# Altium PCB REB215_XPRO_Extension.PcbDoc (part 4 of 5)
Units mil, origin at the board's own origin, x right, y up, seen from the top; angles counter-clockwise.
Board outline 4055.74 x 2606 mil, 6 copper layers (Top Layer LF-signals, Signal Layer 1, Internal Plane 1, Mid-1, Mid-2, Bottom Layer LF-signals), stack 58.434 mil thick; 278 components, 292 nets, 1282 pads, 1177 vias.
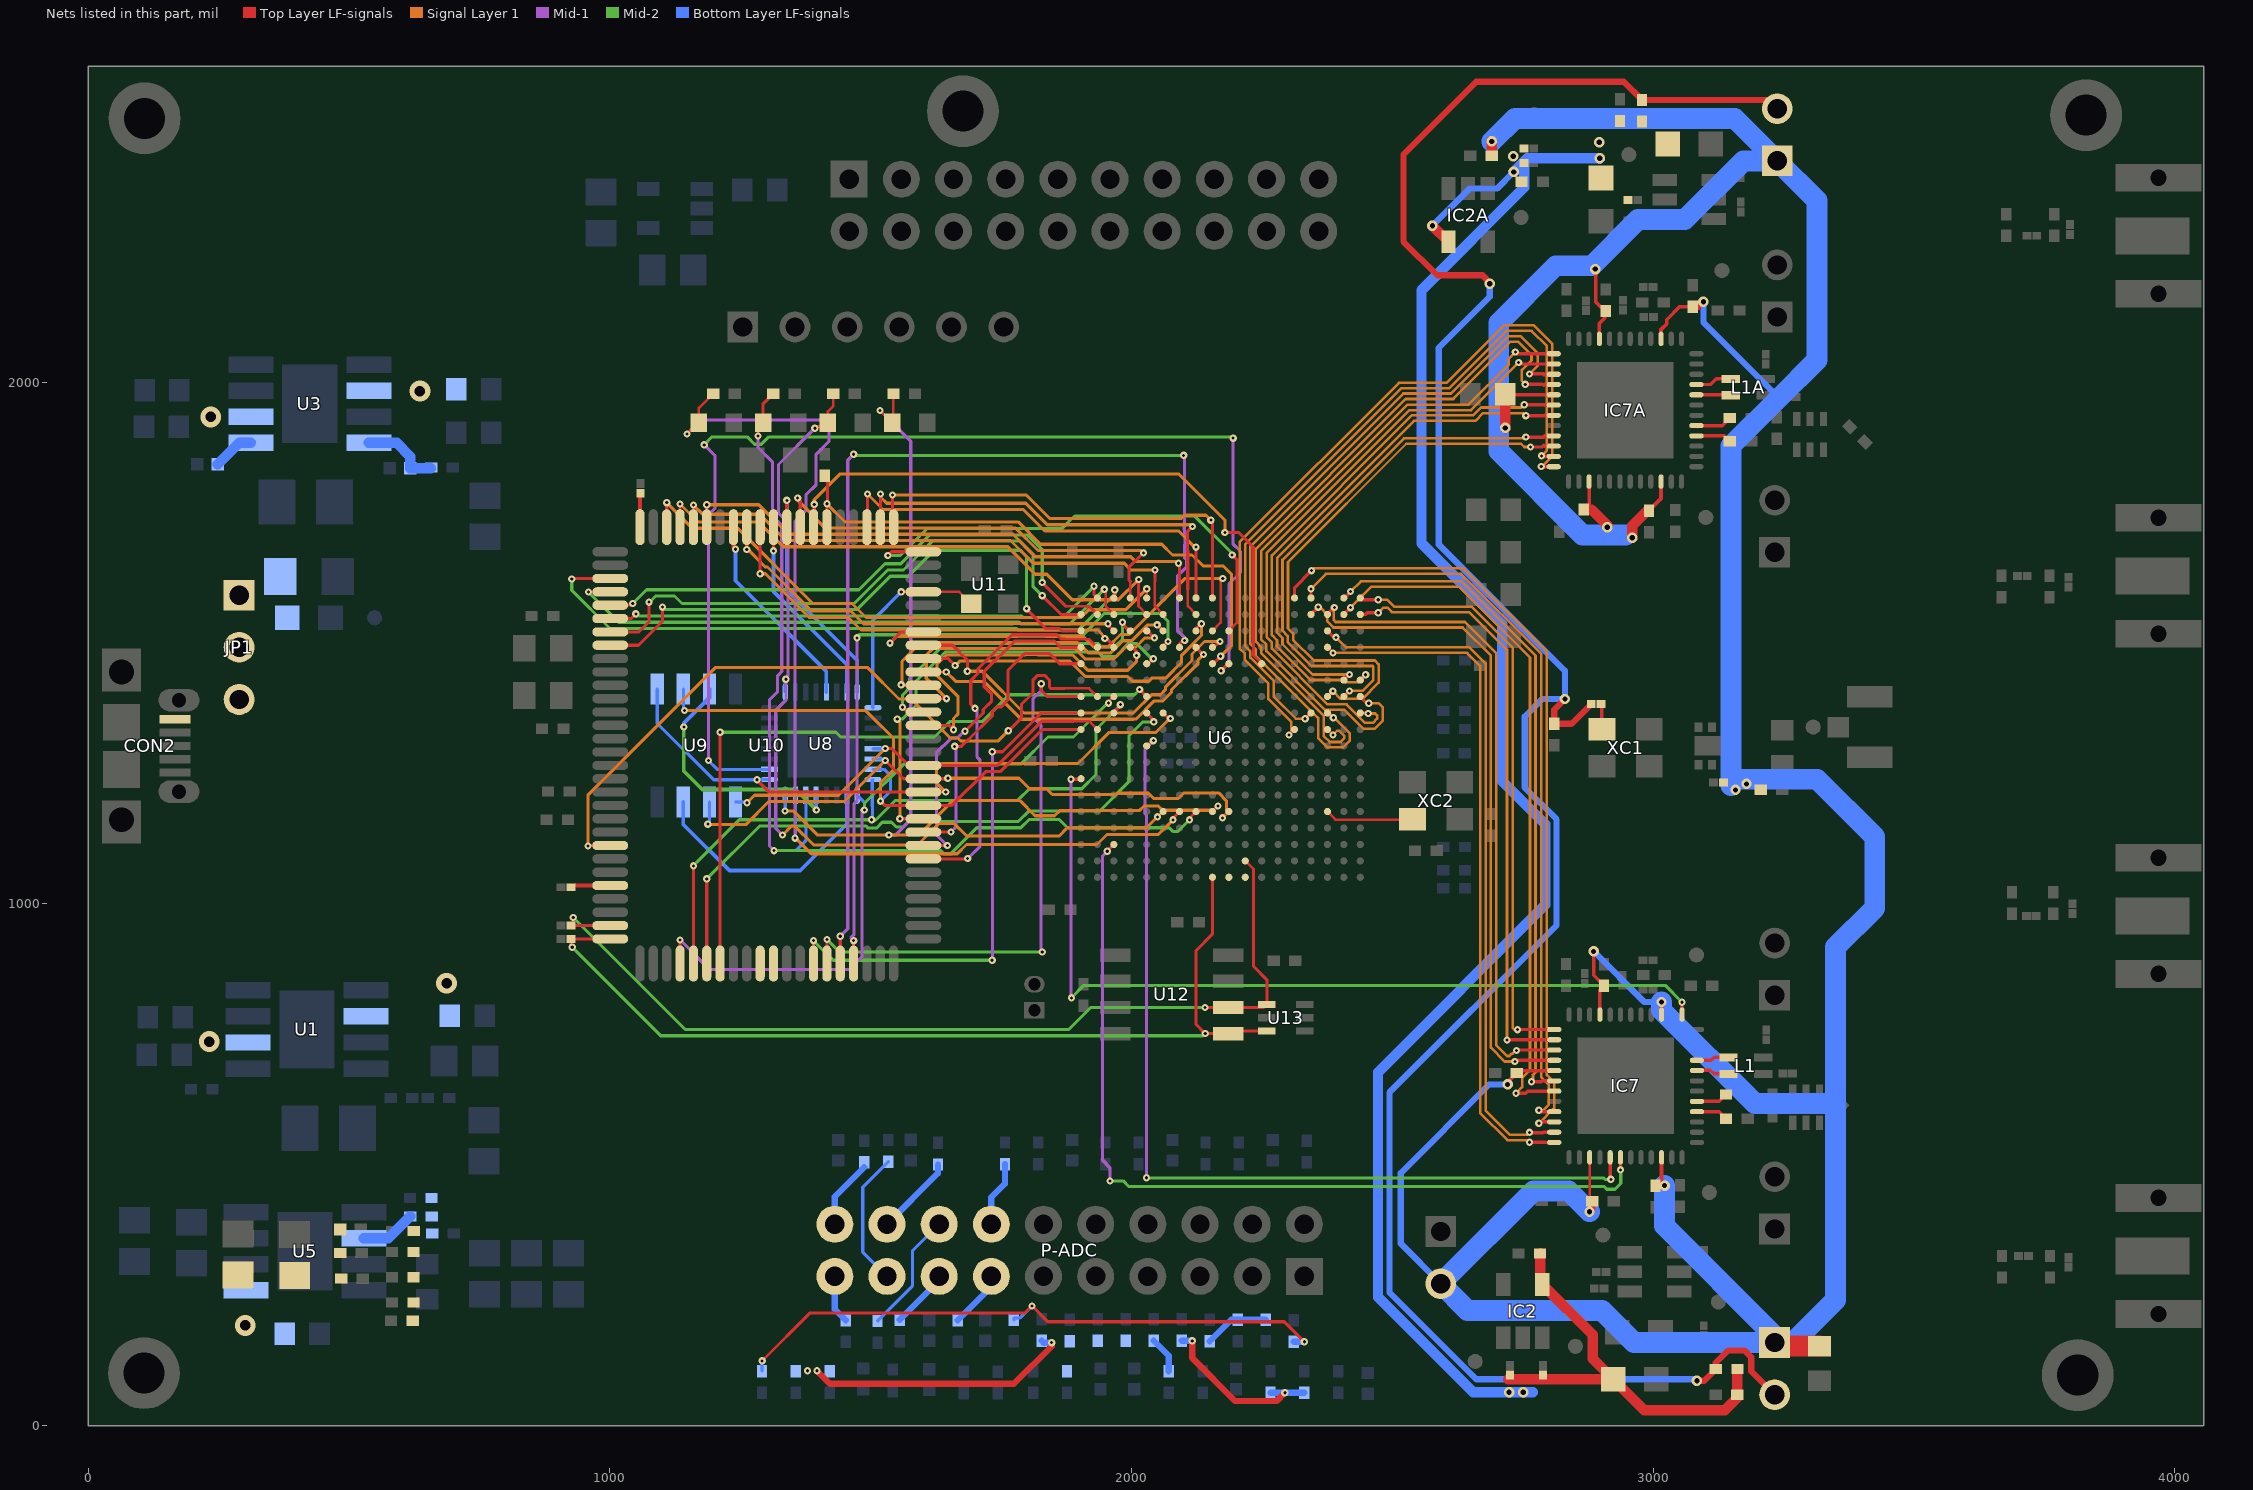
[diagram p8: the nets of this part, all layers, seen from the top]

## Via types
v1: diameter 20, hole 10, Top Layer LF-signals to Bottom Layer LF-signals, 660 vias
v2: diameter 14, hole 6, Top Layer LF-signals to Bottom Layer LF-signals, 470 vias
v3: diameter 40, hole 20, Top Layer LF-signals to Bottom Layer LF-signals, 46 vias
v4: diameter 12, hole 6, Top Layer LF-signals to Bottom Layer LF-signals, 1 vias

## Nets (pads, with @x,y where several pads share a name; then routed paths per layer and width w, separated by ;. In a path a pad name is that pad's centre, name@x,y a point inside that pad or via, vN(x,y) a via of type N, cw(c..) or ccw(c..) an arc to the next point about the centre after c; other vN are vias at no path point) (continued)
NetR17_2: R17.2 U3.5 | length 80.3
  Bottom Layer LF-signals w20: R17.2@248.69,1843 289.47,1883.78 U3.5@312.07,1883.78
NetR018_1: R018.1 U10.100 | length 65.5
  Top Layer LF-signals w7: U10.100@1057.89,1722.31 1057.89,1786.19 R018.1@1059,1787.3
NetR18_1: R18.1 R19.2 U3.4 | length 151.6
  Bottom Layer LF-signals w20: U3.4@538.06,1883.78 591.22,1883.78 617.49,1857.51 R19.2@617.49,1835.41 R18.1@656.71,1835.41
NetR019_1: R019.1 U10.26 | length 72.1
  Top Layer LF-signals w7: R019.1@928.74,1035.3 U10.26@1000.8,1035.3
NetR23_1: R23.1 R24.2 R25.1
NetR23_2: R23.2 U5.6 | length 106.1
  Bottom Layer LF-signals w20: U5.6@528.66,359.18 575.67,359.18 R23.2@617.49,401
NetR40_2: R40.2 R58.2 R65.1 | length 1202.9
  Top Layer LF-signals w6: v2@1291.68,123.68 1384,216 1795.82,216 v2(1809.24,229.42) 1839.66,199 2293,199 v2(2331.41,160.59)
  Bottom Layer LF-signals w6: R58.2@1291.68,104.36 1291.68,123.68 v2(1292,124) ; R40.2@1774.48,202.79 1774.48,206.52 1786.68,206.52 1809.24,229.08 v2(1809.24,229.42) 1810.82,231 v2@1811.16,231
  Bottom Layer LF-signals w12: R65.1@2311.1,160.47 2331.29,160.47 v2(2331.41,160.59)
NetR41_2: R41.2 R57.2 R64.1 | length 124.4
  Bottom Layer LF-signals w12: R64.1@2150.11,161.45 2191.45,202.79 R41.2@2203.77,202.79 R57.2@2257.44,202.79
NetR42_2: R42.2 R56.2 R63.1 | length 336.3
  Top Layer LF-signals w12: v2(2116.49,162.43) 2116.49,129.51 2199,47 2277.98,47 v2(2294,63.03)
  Bottom Layer LF-signals w12: R63.1@2096.45,162.43 v2(2116.49,162.43) ; R42.2@2266.46,63.03 v2(2294,63.03) R56.2@2331.45,63.03
NetR43_2: R43.2 R55.2 R62.1 | length 70
  Bottom Layer LF-signals w12: R62.1@2042.79,162.43 2071.5,133.72 R43.2@2071.5,104.36
NetR44_2: R44.2 R54.2 R61.1
NetR45_2: R45.2 R53.2 R60.1 | length 518.3
  Top Layer LF-signals w12: v2(1397,105) 1422,80 1774.74,80 1847,152.26 v2(1847,159)
  Bottom Layer LF-signals w6: v2(1847,159) v2@1847,160.04
  Bottom Layer LF-signals w12: R60.1@1828.14,162.43 1831.58,159 v2(1847,159)
  other v2: 1379,105
NetR46_2: 
NetU6_E3: U6.E3 XC2.3 | length 170.3
  Top Layer LF-signals w5: U6.E3@2375.64,1177.04 2390.94,1161.74 2455.51,1161.74 2455.62,1161.63 2468.38,1161.63 2468.49,1161.74 2538.72,1161.74 XC2.3@2538.72,1162.57
NetU8_10: U8.10 U9.7 | length 485.1
  Bottom Layer LF-signals w7: U9.7@1141,1195.47 1141,1152.29 1229.29,1064 1364.82,1064 1454.6,1153.78 U8.10@1454.6,1208.31
NetU8_13: U8.13 U9.3 | length 499.1
  Mid-2 w7: v2(1142,1339) 1142,1254.34 1177,1219.34 1356.66,1219.34 v2(1396,1180)
  Bottom Layer LF-signals w7: v2(1142,1339) 1142,1346.69 1191,1395.69 U9.3@1191,1412 ; U8.13@1395.5,1208.31 1395.5,1180.5 v2(1396,1180) 1396,1187.84
NetW2_1: W2.1 XC1.4 | length 46.4
  Top Layer LF-signals w7: XC1.4@2901.88,1335 W2.1@2901.88,1381.44
PA0: U6.R15 U10.67 | length 650.7
  Top Layer LF-signals w6: U10.67@1601.2,1342.39 1650.61,1342.39 v2(1659,1334) ; U6.R15@1997.69,1492 2001,1492 2009.91,1483.1 v2(2009.91,1476.51)
  Signal Layer 1 w6: v2(1659,1334) 1659,1355.39 1658.95,1355.45 1667.17,1363.67 1667.17,1398.09 1627,1438.26 1627,1459.34 1645.13,1477.47 1797.14,1477.47 1797.48,1477.81 1820.52,1477.81 1820.86,1477.47 1886.99,1477.47 1916.46,1448 1993,1448 2009.91,1464.91 v2(2009.91,1476.51)
PA1: U6.T15 U10.68 | length 613
  Top Layer LF-signals w6: v2(1561,1377) 1566,1372 1605.22,1372 U10.68@1601.2,1367.98 ; v2(1983,1540) 1983,1536 1995.5,1523.5 U6.T15@1997.69,1523.5
  Mid-2 w6: v2(1561,1377) 1561,1400.06 1574.36,1413.41 1574.36,1431.27 1642.08,1499 1936.51,1499 1942.41,1493.1 1968.09,1493.1 1983,1508 v2(1983,1540)
PA2: U6.T14 U10.69 | length 632.5
  Top Layer LF-signals w6: U10.69@1601.2,1393.57 v2(1645.57,1393.57) ; U6.T14@2029.19,1523.5 2030.5,1523.5 v2(2044,1510)
  Signal Layer 1 w6: v2(1645.57,1393.57) 1606.54,1432.6 1606.54,1477.09 1618.82,1489.38 1792.21,1489.38 1792.55,1489.72 1825.45,1489.72 1825.79,1489.38 1891.92,1489.38 1912.02,1469.28 1965.45,1469.28 1988.81,1492.64 2008.64,1492.64 2026,1510 v2(2044,1510)
PA3: U6.T13 U10.70 | length 640.2
  Top Layer LF-signals w6: v2(1558.45,1420) 1559.29,1419.16 U10.70@1601.2,1419.16 ; v2(2049.18,1535) U6.T13@2060.68,1523.5
  Signal Layer 1 w6: v2(1558.45,1420) 1560,1421.55 1560,1465.1 1596.19,1501.28 1787.28,1501.28 1787.62,1501.62 1830.38,1501.62 1830.72,1501.28 1896.86,1501.28 1916.95,1481.19 1960.52,1481.19 1983.88,1504.55 2000.55,1504.55 2031,1535 v2(2049.18,1535)
PA4: U6.R11 U10.71 | length 657.6
  Top Layer LF-signals w6: U10.71@1601.2,1444.75 v2(1644.98,1444.75) ; U6.R11@2123.67,1492 2137.67,1478 v2(2138,1478)
  Signal Layer 1 w6: v2(1644.98,1444.75) 1663.17,1426.57 1716.6,1426.57 1789.05,1354.11 2003.86,1354.11 2004.07,1354.32 2008.78,1354.32 2043.65,1389.19 2060.52,1389.19 2076.81,1405.48 2076.81,1410.64 2127.84,1461.67 2127.84,1467.84 v2(2138,1478) 2135.67,1478 v2@2133.67,1480
PA5: U6.T11 U10.72 | length 643.7
  Top Layer LF-signals w6: U10.72@1601.2,1470.34 1648.66,1470.34 v2(1662,1457) ; U6.T11@2123.67,1523.5 2123.67,1526.67 2123,1527.35 2132.65,1537 v2(2134,1537)
  Signal Layer 1 w6: v2(1662,1457) 1670.57,1465.57 1802.07,1465.57 1802.41,1465.91 1815.59,1465.91 1815.93,1465.57 1882.06,1465.57 1911.72,1435.91 1992.59,1435.91 2001.59,1426.91 2032.98,1426.91 2038.98,1432.91 2065.4,1432.91 2096.18,1463.68 2096.18,1476.68 2134,1514.51 v2(2134,1537)
PA6: U6.R10 U10.73 | length 721.5
  Top Layer LF-signals w6: U10.73@1601.2,1495.93 1657.07,1495.93 1685.35,1467.65 v2(1685.35,1446) ; U6.R10@2155.17,1492 2158,1492 2169.14,1503.14 v2(2169.81,1503.14)
  Signal Layer 1 w6: v2(1685.35,1446) 1714,1446 1793.98,1366.02 1998.93,1366.02 1999.14,1366.22 2003.84,1366.22 2038.72,1401.1 2055.59,1401.1 2064.91,1410.41 2064.91,1415.58 2115.93,1466.6 2115.93,1479.09 2139.98,1503.14 v2(2169.81,1503.14)
PA7: U6.T10 U10.74 | length 886.6
  Top Layer LF-signals w5: U6.T10@2155.17,1523.5 2170.92,1539.24 v2@2170.92,1618.38
  Top Layer LF-signals w6: v2(1537,1500) 1558.52,1521.52 U10.74@1601.2,1521.52 ; v2@2170.92,1619.92 v2(2175,1624)
  Signal Layer 1 w6: v2(1537,1500) 1550.19,1513.19 1782.35,1513.19 1782.69,1513.53 1835.31,1513.53 1835.65,1513.19 1907.11,1513.19 1927.2,1493.1 1955.59,1493.1 1978.95,1516.45 1995.62,1516.45 2103.16,1624 v2(2175,1624)
PB0: U6.M16 U8.9 U10.34 | length 1325.3
  Top Layer LF-signals w6: U10.34@1134.66,885.69 v2(1134.66,931) ; v2(1956,1385) 1956,1388 1965.51,1397.51 U6.M16@1966.19,1397.51
  Mid-1 w6: v2(1134.66,931) 1191.66,874 1459,874 1483.24,898.24 1483.24,1179.76 1483.49,1180 v2(1488,1180)
  Mid-2 w6: v2(1488,1180) 1488,1192.54 1563.47,1268 1788,1268 1840,1320 1889,1320 1954,1385 v2(1956,1385)
  Bottom Layer LF-signals w6: U8.9@1474.3,1208.31 1488,1194.61 v2(1488,1180)
PB1: U6.L16 U8.8 U10.35 | length 1287.4
  Top Layer LF-signals w6: U10.35@1160.25,885.69 v2(1160.25,1073) ; U6.L16@1966.19,1366.02 1966.19,1367.19 1980,1381 1979.02,1381.98 v2(1978.66,1381.98)
  Mid-2 w6: v2(1160.25,1073) 1160.25,1073.25 1248.27,1161.27 v2(1502,1161.27) 1510.27,1161.27 1547.53,1198.53 1782.03,1198.53 1804.41,1220.91 1904.91,1220.91 1932,1248 1932,1334.51 1979.48,1381.98 v2(1978.66,1381.98)
  Bottom Layer LF-signals w6: v2(1502,1161.27) 1503.91,1163.17 1503.91,1186.59 1503.09,1187.4 1503.09,1237.1 U8.8@1504.35,1238.36
PB2: U6.L14 U10.36 | length 1228.9
  Top Layer LF-signals w6: U10.36@1185.84,885.69 v2(1185.84,1048) ; U6.L14@2029.19,1366.02 2042.79,1352.41 v2(2042.79,1349)
  Mid-2 w6: v2(1185.84,1048) 1287.21,1149.36 1491.41,1149.36 1495.41,1145.36 1511.2,1145.36 1522.5,1156.66 1540.09,1156.66 1549.41,1147.35 1562.59,1147.35 1573.24,1158 1783,1158 1802.97,1177.97 1938.67,1177.97 1995,1234.31 1995,1321.91 2022.09,1349 v2(2042.79,1349)
PB3: U6.M14 U10.37 | length 1305.5
  Top Layer LF-signals w6: U10.37@1211.43,885.69 v2(1211.43,1329) ; v2(2015.7,1411) U6.M14@2029.19,1397.51
  Mid-2 w6: v2@1215,1326.98 1217.02,1329 1433.48,1329 1442.48,1320 1622.51,1320 1652.41,1349.91 1714.74,1349.91 1733.09,1368.26 1733.09,1368.59 1742.41,1377.91 1742.74,1377.91 1765.93,1401.1 2005.79,1401.1 v2(2015.7,1411)
PB4: U6.L18 U10.44 | length 1003.1
  Top Layer LF-signals w6: U10.44@1390.57,885.69 v2(1390.57,929.57) ; v2(1733.1,1291.79) 1752.7,1291.79 1826.92,1366.02 U6.L18@1903.2,1366.02
  Mid-1 w6: v2(1733,892) 1733.72,892.72 1733.72,1291.17 v2(1733.1,1291.79)
  Mid-2 w6: v2(1390.57,929.57) 1428.13,892 v2(1733,892)
PB5: U6.M18 U10.45 | length 1091.5
  Top Layer LF-signals w6: U10.45@1416.16,885.69 v2(1416.16,931.98) ; v2(1827,1422.18) 1827,1409.13 1838.49,1397.65 ; 1838.49,1397.51 1838.49,1397.65 ; U6.M18@1903.2,1397.51 1838.62,1397.51 1838.49,1397.65
  Mid-1 w6: v2(1827,1422.18) 1827,1409 1810.99,1392.99 1810.99,1358.21 1826.91,1342.3 1826.91,910.1 v2(1829,908)
  Mid-2 w6: v2(1416.16,931.98) 1440.14,908 v2(1829,908)
PB6: U6.R12 U10.46 | length 2014.1
  Top Layer LF-signals w6: U10.46@1441.75,885.69 v2(1441.75,938) ; U6.R12@2089,1492 U6.R12@2092.18,1492 2092.18,1498.92 2098.26,1505 v2(2102,1505)
  Mid-1 w6: v2(1441.75,938) 1456,952.25 1456,1850.66 v2(1467.34,1862) ; v2(2100.09,1859.91) 2102,1858 2102,1730.87 2101.09,1729.97 2101.09,1716.79 2102,1715.88 2102,1703.49 2102.91,1702.59 2102.91,1689.41 2102,1688.51 2102,1663.49 2105.91,1659.59 2105.91,1646.41 2088,1628.51 2088,1524.33 2102,1510.33 v2(2102,1505)
  Mid-2 w6: v2@1467.34,1859.91 v2(2100.09,1859.91)
PB7: U6.R13 U10.47 | length 1315.8
  Top Layer LF-signals w6: U10.47@1467.34,885.69 v2(1467.34,929.66) ; U6.R13@2060.68,1492 2060.68,1494.15 2061.15,1494.15 v2(2070,1503) v2@2072,1505
  Mid-1 w6: v2(1467.34,929.66) 1462,935 1467.91,940.91 1467.91,1191.4 1474,1197.49 v2(1474,1510)
  Mid-2 w6: v2(1474,1510) 1472.19,1510 1478.28,1516.1 1774.9,1516.1 1777.62,1513.38 1904.38,1513.38 1947.7,1556.7 2055.3,1556.7 2070,1542 v2(2070,1503)
PC0: U6.R17 U10.57 | length 737.5
  Top Layer LF-signals w5: 1871.31,1507.75 1918.95,1507.75 U6.R17@1934.7,1492
  Top Layer LF-signals w6: U10.57@1601.2,1086.48 1685.48,1086.48 v2(1686,1087) ; v2(1700,1375) 1692,1383 1692,1428 1705.93,1441.93 1705.93,1450.77 1771.1,1515.93 1857.28,1515.93 1865.46,1507.75 1871.31,1507.75
  Mid-1 w6: v2(1686,1087) 1709.91,1110.91 1709.91,1275.65 1704.09,1281.46 1704.09,1370.91 v2(1700,1375)
PC1: U6.R18 U10.58 | length 661.2
  Top Layer LF-signals w6: U10.58@1601.2,1112.07 1646.93,1112.07 v2(1647,1112) ; v2(1681,1331) 1715.91,1365.91 1715.91,1372.82 1731.91,1388.82 1731.91,1402 1717.84,1416.07 1717.84,1445.84 1776.03,1504.03 1852.35,1504.03 1864.38,1492 U6.R18@1903.2,1492
  Mid-1 w6: v2(1647,1112) 1626,1133 1626,1289.49 1654.41,1317.91 1665.91,1317.91 1680,1332 v2(1681,1331)
PC2: U6.P18 U10.59 | length 583.2
  Top Layer LF-signals w6: U10.59@1601.2,1137.66 1653.66,1137.66 v2(1654,1138) ; v2(1661,1302) 1674,1302 1687.09,1315.1 1687.59,1315.1 1733.09,1360.6 1733.09,1368.59 1742.41,1377.91 1750.4,1377.91 1763.43,1390.94 1763.43,1447.76 1795.89,1480.22 1842.49,1480.22 1862.2,1460.5 U6.P18@1903.2,1460.5
  Mid-1 w6: v2(1654,1138) 1663.95,1147.95 v2@1663.95,1299.05 ; v2@1661,1299.05 v2(1661,1302)
PC3: U6.P14 U10.60 | length 853.3
  Top Layer LF-signals w6: v2(1556,1163.25) U10.60@1601.2,1163.25 ; U6.P14@2029.19,1460.5 2032.5,1460.5 v2(2042,1470)
  Mid-2 w6: v2(1551,1354.18) 1560.68,1354.18 1587,1380.51 1587,1427.08 1642.83,1482.91 1935.76,1482.91 1944.67,1474 1969.55,1474 1994.96,1499.41 2009.49,1499.41 v2@2038.9,1470 ; v2@2038.51,1470 v2@2038.9,1470 ; v2(2042,1470) v2@2038.9,1470
  Signal Layer 1 w6: v2(1551,1354.18) 1556,1349.18 v2(1556,1163.25)
PC4: U6.K18 U8.7 U9.2 U10.61 | length 1136.4
  Top Layer LF-signals w6: v2(1519,1197) 1527.16,1188.84 U10.61@1601.2,1188.84 1655.68,1188.84 1720.55,1253.71 1748.29,1253.71 1829.1,1334.52 U6.K18@1903.2,1334.52
  Signal Layer 1 w6: v2(1143,1371) 1490,1371 1543.97,1317.03 1543.97,1257.3 1519,1232.33 v2(1519,1197)
  Bottom Layer LF-signals w6: v2@1141,1373 U9.2@1141,1412 ; U8.7@1504.35,1258.06 1525.94,1258.06 1538.38,1245.62 1538.38,1216.38 v2(1519,1197)
PC5: U6.L13 U8.17 U9.1 U10.62 | length 1260.4
  Top Layer LF-signals w6: v2@1285.84,1238.36 1282.36,1238.36 v2(1282,1238) 1305.57,1214.43 U10.62@1601.2,1214.43 v2(1644,1214.43) ; U6.L13@2060.68,1366.02 2060.68,1366.68 2071.76,1355.6 v2(2074.6,1355.6)
  Signal Layer 1 w6: v2(1644,1214.43) 1626,1232.43 1626,1257.53 1637.57,1269.1 1897.56,1269.1 1957.37,1328.91 2046.91,1328.91 2073.6,1355.6 v2(2074.6,1355.6)
  Bottom Layer LF-signals w6: U9.1@1091,1412 1091,1346 1199,1238 v2(1282,1238) ; v2@1282.36,1238.36 U8.17@1306.35,1238.36
PC6: U6.E9 U8.6 U9.6 U10.63 | length 1205.2
  Top Layer LF-signals w6: v2@1528,1275 1562.98,1240.02 U10.63@1601.2,1240.02 1649.02,1240.02 v2(1648.05,1241) ; v2(2174.63,1165) U6.E9@2186.67,1177.04
  Signal Layer 1 w6: v2(1188,1153) 1188,1152 1260.59,1152 1304.99,1196.4 1449.4,1196.4 v2(1528.07,1275.07) ; v2(1648.05,1241) 1784.32,1241 1804.41,1220.91 1837.41,1220.91 1848.41,1209.91 1970.6,1209.91 1972.89,1212.2 2032.31,1212.2 2042.51,1202 2089.79,1202 2100.7,1212.91 2167.09,1212.91 2182,1198 2182,1172.37 v2(2174.63,1165)
  Bottom Layer LF-signals w6: v2@1191,1156 U9.6@1191,1195.47 ; U8.6@1504.35,1277.76 v2@1525.38,1277.76
PC7: U6.K17 U8.5 U9.5 U10.64 | length 814.2
  Top Layer LF-signals w5: 1889.21,1350.27 1918.95,1350.27 U6.K17@1934.7,1334.52
  Top Layer LF-signals w6: v2(1528,1298) 1540.25,1298 1572.64,1265.61 U10.64@1601.2,1265.61 1743.36,1265.61 1828.01,1350.27 1889.21,1350.27
  Signal Layer 1 w6: v2(1263,1194) 1277.31,1208.31 1438.31,1208.31 v2(1528,1298)
  Bottom Layer LF-signals w6: U9.5@1241,1195.47 v2@1261.54,1195.47 ; U8.5@1504.35,1297.46 1527.46,1297.46 v2(1528,1298)
PD0: U6.T9 U10.80 | length 951.2
  Top Layer LF-signals w5: U6.T9@2186.67,1523.5 2202.41,1539.24 2202.41,1618.38
  Top Layer LF-signals w6: v2(1533,1668) 1540.06,1675.06 U10.80@1601.2,1675.06 ; v2(2193,1669) 2202.41,1659.59 2202.41,1618.38
  Mid-2 w6: v2(1533,1668) 1557,1668 1609,1720 1867,1720 1886.09,1739.1 1887.59,1739.1 1892.51,1744.02 2120.66,1744.02 2193,1671.68 v2(2193,1669)
PD1: U6.V10 U10.81 | length 848.5
  Top Layer LF-signals w6: v2(1542,1784) 1542,1724.42 U10.81@1544.11,1722.31 ; v2(2152.25,1735.75) 2155.17,1732.83 U6.V10@2155.17,1586.49
  Signal Layer 1 w6: v2(1542,1784) 1798.51,1784 1843.79,1738.72 2094.79,1738.72 2101.08,1745 2143,1745 v2(2152.25,1735.75)
PD2: U6.U11 U10.82 | length 866.7
  Top Layer LF-signals w5: 2107.93,1603 2107.93,1570.74 U6.U11@2123.67,1554.99
  Top Layer LF-signals w6: U10.82@1518.52,1722.31 1519,1722.79 v2(1519,1785.84) ; 2107.93,1603 2107.93,1677.25 2107.77,1677.41 2107.77,1714.15 v2(2117,1723.38)
  Signal Layer 1 w6: v2(1519,1785.84) 1519,1780 1530.91,1768.1 1797.58,1768.1 1838.86,1726.81 v2@2113.57,1726.81 ; v2@2115.26,1722.31 v2@2115.93,1722.31 ; v2@2115.93,1723.38 v2(2117,1723.38)
PD3: U6.V11 U10.83 | length 831.2
  Top Layer LF-signals w5: U6.V11@2123.67,1586.49 2123.67,1618.38
  Top Layer LF-signals w6: U10.83@1492.93,1722.31 1494,1723.38 v2(1494,1785.84) ; 2123.67,1618.38 v2(2123.67,1684)
  Signal Layer 1 w6: v2(1494,1785.84) 1523.65,1756.19 1792.64,1756.19 1833.93,1714.91 2090.59,1714.91 v2@2121.49,1684
PD4: U6.V12 U10.95 | length 1062.6
  Top Layer LF-signals w5: U6.V12@2092.18,1586.49 2092.18,1602.43
  Top Layer LF-signals w6: U10.95@1185.84,1722.31 v2(1185.84,1765.16) ; v2(2090,1653) 2092.18,1650.82 2092.18,1602.43
  Signal Layer 1 w6: v2(1185.84,1765.16) 1285.84,1765.16 1342.43,1708.57 1772.92,1708.57 1815.89,1665.6 1998.59,1665.6 2008.09,1656.1 2089.91,1656.1 2090,1656 v2(2090,1653)
PD5: U6.U13 U10.96 | length 1070.5
  Top Layer LF-signals w5: 2044.93,1618.38 2044.93,1570.74 U6.U13@2060.68,1554.99
  Top Layer LF-signals w6: U10.96@1160.25,1722.31 v2(1160.25,1764.79) ; 2044.93,1618.38 2044.93,1639.93 v2(2045,1640)
  Signal Layer 1 w6: v2(1160.25,1764.79) 1178.05,1747 1287.16,1747 1337.5,1696.66 1767.99,1696.66 1811.65,1653 1986.19,1653 1999.19,1640 v2(2045,1640)
PD6: U6.U14 U10.97 | length 1096.9
  Top Layer LF-signals w5: v2@2013.44,1618.38 2013.44,1570.74 U6.U14@2029.19,1554.99
  Top Layer LF-signals w6: U10.97@1134.66,1722.31 v2(1134.66,1766.71) ; v2@2013.44,1618.38 2013.44,1625.56 2014,1625 v2(2014,1622)
  Signal Layer 1 w6: v2(1134.66,1766.71) 1169.37,1732 1285.33,1732 1332.57,1684.76 1763.06,1684.76 1815.91,1631.91 1837.91,1631.91 1886.81,1583 1975,1583 v2(2014,1622)
PD7: U6.V14 U10.98 | length 1098.7
  Top Layer LF-signals w5: U6.V14@2029.19,1586.49 v2(2029.19,1604)
  Top Layer LF-signals w6: U10.98@1109.07,1722.31 v2(1109.07,1769.33)
  Signal Layer 1 w6: v2(1109.07,1769.33) 1158.31,1720.1 1244.97,1720.1 1389.06,1576 1464.17,1576 1491.07,1549.1 1767.74,1549.1 1767.89,1549.24 1850.11,1549.24 1850.26,1549.1 1903.09,1549.1 1918,1564 1989.19,1564 v2(2029.19,1604)
PE0: R15B.2 U6.P10 U10.86 | length 1119.7
  Top Layer LF-signals w6: R15B.2@1412.25,1820.66 1417,1815.91 1417,1767.89 v2(1416.16,1767.05) U10.86@1416.16,1722.31 ; U6.P10@2155.17,1460.5 2156.5,1460.5 v2(2170.92,1474.92)
  Signal Layer 1 w6: v2(1416.16,1767.05) 1450.83,1732.38 1782.78,1732.38 1825.75,1689.41 2058.14,1689.41 2078.55,1669 2116.18,1669 2137.18,1648 2175.53,1648 2192,1631.53 2192,1496 v2(2170.92,1474.92)
PE1: U6.P7 U10.87 | length 1217.6
  Top Layer LF-signals w5: 2233.91,1618.38 2233.91,1476.25 U6.P7@2249.66,1460.5
  Top Layer LF-signals w6: U10.87@1390.57,1722.31 1392,1723.74 v2(1392,1766) ; v2(2179,1712) 2206,1712 2233.91,1684.09 2233.91,1618.38
  Signal Layer 1 w6: v2(1392,1766) 1392,1775.13 1440.77,1823.91 2091.01,1823.91 2179,1735.92 v2(2179,1712)
PE2: U6.V15 U10.88 | length 865.9
  Top Layer LF-signals w5: U6.V15@1997.69,1586.49 1997.69,1618.38
  Top Layer LF-signals w6: v2(1360,1778) 1364.98,1773.02 U10.88@1364.98,1722.31 ; 1997.69,1618.38 1995.09,1620.97 1995.09,1645.1 v2(2023,1673)
  Signal Layer 1 w6: v2(1360,1778) 1360,1773.64 1413.17,1720.47 1777.85,1720.47 1820.82,1677.5 2018.5,1677.5 v2(2023,1673)
PE3: U8.32 U10.89 | length 474.5
  Top Layer LF-signals w7: U10.89@1339.39,1722.31 v2(1339.39,1773.61)
  Bottom Layer LF-signals w7: v2(1339.39,1773.61) 1339.39,1601.61 1474.3,1466.7 U8.32@1474.3,1406.31
PE4: U8.31 U10.90 | length 374.3
  Top Layer LF-signals w6: v2(1313.8,1676.86) U10.90@1313.8,1722.31
  Bottom Layer LF-signals w7: v2(1313.8,1676.86) 1313.8,1599.09 1454.6,1458.28 U8.31@1454.6,1406.31
PE5: U6.R16 U10.91 | length 832.2
  Top Layer LF-signals w6: v2(1288.21,1633) U10.91@1288.21,1722.31 ; v2(1949,1509) 1952,1509 1966.19,1494.81 U6.R16@1966.19,1492
  Signal Layer 1 w6: v2(1288.21,1633) 1298.39,1633 1382.29,1549.1 1457.4,1549.1 1481.4,1525.1 1777.42,1525.1 1777.76,1525.43 1840.25,1525.43 1840.58,1525.1 1935.07,1525.1 1952.26,1507.91 v2@1953.09,1507.91
PE6: U6.T16 U10.92 | length 814.8
  Top Layer LF-signals w6: v2(1262.61,1679.61) U10.92@1262.61,1722.31 ; v2(1955,1537) 1955,1534.69 U6.T16@1966.19,1523.5
  Signal Layer 1 w6: v2(1262.61,1679.61) 1264.08,1679.61 1297.7,1646 1302.23,1646 1386.23,1562 1461.33,1562 1486.33,1537 1772.49,1537 1772.82,1537.34 1845.18,1537.34 1845.52,1537 v2(1955,1537) v2@1956.6,1538.6
PE7: U8.29 U10.93 | length 391.8
  Top Layer LF-signals w7: U10.93@1237.02,1722.31 1237.02,1683.98 v2(1241,1680) v2@1239,1680
  Bottom Layer LF-signals w7: v2(1241,1680) 1241,1619.59 1415.2,1445.39 U8.29@1415.2,1406.31
PROG_B: U6.P9 U8.18 | length 2263.8
  Top Layer LF-signals w6: v2(2172,1447) 2185.5,1460.5 U6.P9@2186.67,1460.5
  Mid-1 w6: v2(1181,1880) 1201.75,1859.25 1201.75,1758.57 1189,1745.82 v2(1189,1275) ; v2(2172,1447) 2187.09,1462.1 2187.09,1613.6 2208.91,1635.41 2208.91,1675.59 2194.91,1689.59 v2(2194.91,1893)
  Mid-2 w6: v2(1181,1880) 1181,1880.42 1195.91,1895.32 1263.18,1895.32 1277.41,1881.1 1290.59,1881.1 1304.82,1895.32 2192.58,1895.32 v2(2194.91,1893)
  Bottom Layer LF-signals w6: v2(1189,1275) 1205.94,1258.06 U8.18@1306.35,1258.06
R\E\S\E\T\: U8.1 U10.77 U11.2 | length 387.8
  Top Layer LF-signals w5: U10.77@1601.2,1598.29 1669.87,1598.29 U11.2@1692.57,1575.6
  Top Layer LF-signals w7: v2(1558.7,1598.29) U10.77@1601.2,1598.29
  Bottom Layer LF-signals w7: U8.1@1504.35,1376.26 1504.35,1543.94 v2(1558.7,1598.29)
R\S\T\N\: IC7.13@3055.51,787.82 U6.G18 | length 1659.6
  Top Layer LF-signals w6: v2(1884,1239) 1902.17,1239 U6.G18@1903.2,1240.03 ; IC7.13@3055.51,787.82 v2(3055.51,811.49)
  Mid-1 w6: v2(1884,1239) 1884,822.2 1882,820.2 1882.2,820 v2(1885,820)
  Mid-2 w6: v2@1885,820.42 1908.41,843.83 3023.17,843.83 v2(3055.51,811.49)
RDX0: U10.41
RDY0: U6.V16 U10.3 | length 1221
  Top Layer LF-signals w6: v2(927,1622.88) 928,1623.88 U10.3@1000.8,1623.88 ; U6.V16@1966.19,1586.49 1966.19,1592.43 1966,1592.62 1968,1594.62 v2(1968,1602)
  Mid-2 w6: v2(927,1622.88) 927,1601.42 1000.42,1528 1779.83,1528 1782.55,1525.28 1899.05,1525.28 1968,1594.24 v2(1968,1602)
RDY1: U6.U16 U10.4 | length 1140.9
  Top Layer LF-signals w5: v2@1950.45,1603 1950.45,1570.74 U6.U16@1966.19,1554.99
  Top Layer LF-signals w6: v2@962,1598 v2(959,1598) 959.29,1598.29 U10.4@1000.8,1598.29
  Mid-2 w6: v2(959,1598) 1017.09,1539.91 1784.76,1539.91 1787.48,1537.19 1882.19,1537.19 v2(1948,1603)
RDY2: U6.U17 U10.5 | length 1089.6
  Top Layer LF-signals w5: 1874.26,1570.74 1918.95,1570.74 U6.U17@1934.7,1554.99
  Top Layer LF-signals w6: U10.5@1000.8,1572.7 1001.1,1573 1041,1573 v2(1044,1576) ; v2(1829,1616) 1874.26,1570.74
  Mid-2 w6: v2(1044,1576) 1070.24,1602.24 1477.76,1602.24 1527.62,1652.1 1557.93,1652.1 1613.31,1707.47 1800.18,1707.47 1829,1678.66 v2(1829,1616)
RDY3: U6.V17 U10.6 | length 988.6
  Top Layer LF-signals w6: U10.6@1000.8,1547.11 1041.11,1547.11 v2(1050,1556) ; v2(1928,1609) 1928,1593.19 U6.V17@1934.7,1586.49
  Mid-2 w6: v2@1050,1551.81 v2(1050,1556) 1054.19,1551.81 1789.7,1551.81 1792.41,1549.1 1869.09,1549.1 1928,1608 v2(1928,1609)
RDY4: U6.U18 U10.7 | length 1102.8
  Top Layer LF-signals w6: U10.7@1000.8,1521.52 1055.85,1521.52 1075,1540.67 v2(1075,1578.5) ; v2(1829,1591) 1865.01,1554.99 U6.U18@1903.2,1554.99
  Mid-2 w6: v2(1075,1578.5) 1076,1578.5 1087.83,1590.33 1124,1590.33 1138.33,1576 1468.36,1576 1532.55,1640.19 1562.86,1640.19 1618.24,1695.57 1785.92,1695.57 1810.91,1670.58 1810.91,1609.1 v2(1829,1591)
RDY5: U6.T18 U10.8 | length 1118.6
  Top Layer LF-signals w6: U10.8@1000.8,1495.93 1054.93,1495.93 1101,1542 v2(1101,1569) ; v2(1799,1566) 1799,1565 1836.16,1527.84 1862.21,1527.84 1866.55,1523.5 U6.T18@1903.2,1523.5
  Mid-2 w6: v2@1101,1564.1 1473.29,1564.1 1537.48,1628.28 1572.28,1628.28 1622,1678 1786.65,1678 1799,1665.65 v2(1799,1566)
RF09_N: IC7.9 L1.4 | length 62.8
  Top Layer LF-signals w6.5: IC7.9@3084.06,700.22 3111.69,700.22 3117.22,705.75 L1.4@3144.54,705.75
RF09_P: IC7.8 L1.1 | length 63.8
  Top Layer LF-signals w6.5: IC7.8@3084.06,680.54 3084.98,681.46 3109.88,681.46 3117.09,674.25 L1.1@3144.54,674.25
RF09A_N: IC7A.9 L1A.4 | length 70.5
  Top Layer LF-signals w6.5: IC7A.9@3083.06,1995.69 3109.9,1995.69 3120.74,2006.53 L1A.4@3149.02,2006.53
RF09A_P: IC7A.8 L1A.1 | length 66.4
  Top Layer LF-signals w6.5: IC7A.8@3083.06,1976 3148.05,1976 L1A.1@3149.02,1975.03
RF24_N: C12.1 IC7.5 | length 61.3
  Top Layer LF-signals w6.5: IC7.5@3084.06,621.48 3126.5,621.48 C12.1@3139.85,634.83
RF24_P: C2.1 IC7.4 | length 61.4
  Top Layer LF-signals w6.5: IC7.4@3084.06,601.8 3126.42,601.8 C2.1@3139.85,588.37
RF24A_N: C12A.1 IC7A.5 | length 72.9
  Top Layer LF-signals w6.5: IC7A.5@3085.03,1914.97 IC7A.5@3083.06,1916.95 3132.69,1916.95 C12A.1@3147.19,1931.44
RF24A_P: C02A.1 IC7A.4 | length 68.2
  Top Layer LF-signals w6.5: IC7A.4@3083.06,1897.26 3136.74,1897.26 C02A.1@3147,1887
RXCLKA_N: IC7A.33 U6.M2 | length 1061.7
  Top Layer LF-signals w6.5: U6.M2@2407.14,1397.51 v2(2418,1408.37) ; v2(2756,1895) 2790.14,1895 2792.4,1897.26 IC7A.33@2809.43,1897.26
  Signal Layer 1 w5: v2(2418,1408.37) 2443.27,1408.37 2463.5,1428.61 2463.5,1455 2462.37,1456.14 2345.32,1456.14 2299.5,1501.96 2299.5,1513.97 2289.5,1523.97 2289.5,1659.75 2522.42,1892.67 2753.67,1892.67 v2(2756,1895) v2@2756,1892.67
RXCLKA_P: IC7A.34 U6.M3 | length 1101.7
  Top Layer LF-signals w6.5: U6.M3@2375.64,1397.51 v2(2386.13,1408) ; v2(2765,1876) 2787.14,1876 2790.56,1879.42 2792.4,1877.58 IC7A.34@2809.43,1877.58
  Signal Layer 1 w5: v2(2386.13,1408) 2401.13,1393 2442.74,1393 2474,1424.26 2474,1459.35 2466.72,1466.64 2349.67,1466.64 2310,1506.31 2310,1518.32 2300,1528.32 2300,1655.4 2526.77,1882.17 2746.83,1882.17 2753,1876 v2(2765,1876)
RXCLKN: IC7.33 U6.V4 | length 1458.9
  Top Layer LF-signals w6.5: v2(2344,1604) 2344.15,1603.85 U6.V4@2344.15,1586.49 ; v2(2781,604.45) 2783.66,601.8 IC7.33@2810.43,601.8
  Signal Layer 1 w5: v2(2344,1604) 2372.91,1632.91 2632.08,1632.91 2785.83,1479.16 2785.83,667.65 2799.93,653.54 2799.93,615 2789.39,604.45 v2(2781,604.45)
RXCLKP: IC7.34 U6.V5 | length 1531.7
  Top Layer LF-signals w6.5: U6.V5@2312.65,1586.49 2312.65,1606.5 v2(2345,1638.85) ; v2(2781,579.45) 2783.66,582.11 IC7.34@2810.43,582.11
  Signal Layer 1 w5: v2@2349.56,1643.41 2636.43,1643.41 2796.33,1483.51 2796.33,672 2810.43,657.89 2810.43,608.43 2781.46,579.45 v2(2781,579.45)
RXD0: U6.A8
RXD24A_N: IC7A.35 U6.L4 | length 1406.8
  Top Layer LF-signals w6.5: v2(2333,1355) 2344.02,1366.02 U6.L4@2344.15,1366.02 ; v2(2786,1859) 2790.61,1859 2792.06,1857.55 2792.4,1857.89 IC7A.35@2809.43,1857.89
  Signal Layer 1 w5: v2(2333,1355) 2315.01,1355 2273.08,1396.93 2273.08,1427.26 2228,1472.34 2228,1484.36 2218,1494.36 2218,1689.37 2517.13,1988.5 2608.5,1988.5 2718.5,2098.5 2766.94,2098.5 2796.33,2069.11 2796.33,1869.33 v2(2786,1859)
RXD24A_P: IC7A.36 U6.K5 | length 1483
  Top Layer LF-signals w6.5: v2@2302,1325 v2(2302,1324) 2302.13,1324 U6.K5@2312.65,1334.52 ; v2(2785.66,1838.55) 2792.06,1838.55 2792.4,1838.21 IC7A.36@2809.43,1838.21
  Signal Layer 1 w5: v2(2302,1324) 2306.58,1328.58 2306.58,1348.58 2262.58,1392.58 2262.58,1422.91 2217.5,1467.99 2217.5,1480.01 2207.5,1490.01 2207.5,1693.72 2512.78,1999 2604.15,1999 2714.15,2109 2771.29,2109 2806.83,2073.46 2806.83,1858.61 2786.76,1838.55 v2(2785.66,1838.55)
RXD24N: IC7.35 U6.T3 | length 1341.9
  Top Layer LF-signals w6.5: U6.T3@2375.64,1523.5 2388.14,1511 v2(2392,1511) ; v2@2760.43,562.08 v2(2763,562.08) 2763.88,561.2 2788.56,561.2 2789.78,562.43 IC7.35@2810.43,562.43
  Signal Layer 1 w5: v2(2392,1511) 2411.08,1491.92 2647.93,1491.92 2679,1460.85 2679,604 2725.17,557.83 2758.75,557.83 v2(2763,562.08)
RXD24P: IC7.36 U6.R3 | length 1335.6
  Top Layer LF-signals w6.5: U6.R3@2375.64,1492 v2(2386.51,1481.14) ; v2@2763,546.83 v2(2763,543.08) 2793.06,543.08 2793.4,542.74 IC7.36@2810.43,542.74
  Signal Layer 1 w5: v2(2386.51,1481.14) 2386.51,1482.51 2387.59,1481.42 2643.58,1481.42 2668.5,1456.5 2668.5,599.65 2720.82,547.33 2758.75,547.33 v2(2763,543.08)
RXDN09: IC7.30 U6.V2 | length 1297.5
  Top Layer LF-signals w6.5: U6.V2@2407.14,1586.49 2408.2,1586.49 v2@2415.48,1593.77 ; v2(2767,659) 2785.63,659 2787.48,660.85 IC7.30@2810.43,660.85
  Signal Layer 1 w5: v2(2420,1599) 2439.56,1618.56 2632.28,1618.56 2774.5,1476.34 2774.5,677.11 2769.7,672.31 2769.7,661.7 v2(2767,659)
RXDN09A_N: IC7A.30 U6.N1 | length 1058.6
  Top Layer LF-signals w6.5: U6.N1@2438.63,1429.01 v2(2449,1439.37) ; v2(2753,1957) 2791.03,1957 2792.06,1955.97 2792.4,1956.32 IC7A.30@2809.43,1956.32
  Signal Layer 1 w5: v2(2449,1439.37) 2434.5,1424.87 2411.79,1424.87 2407.29,1429.37 2343.1,1429.37 2279,1493.47 2279,1505.48 2269,1515.48 2269,1668.24 2537.26,1936.5 2654.94,1936.5 2670.16,1951.72 2747.72,1951.72 v2(2753,1957)
RXDP09: IC7.31 U6.U2 | length 1356.6
  Top Layer LF-signals w6.5: U6.U2@2407.14,1554.99 2420,1567.85 v2(2420,1568) ; v2(2737,637) 2755.69,637 2759.86,641.17 IC7.31@2810.43,641.17
  Signal Layer 1 w5: v2(2420,1568) 2460.06,1608.06 2627.93,1608.06 2764,1471.99 2764,681.46 2749,666.46 2749,649 v2(2737,637)
RXDP09A_P: IC7A.31 U6.N2 | length 985.4
  Top Layer LF-signals w6.5: U6.N2@2407.14,1429.01 v2(2418,1439.87) ; v2(2756,1936) 2791.09,1936 2792.06,1936.97 2792.4,1936.63 IC7A.31@2809.43,1936.63
  Signal Layer 1 w5: v2(2418,1439.87) 2347.45,1439.87 2289.5,1497.82 2289.5,1509.83 2279.5,1519.83 2279.5,1663.89 2541.61,1926 2659.29,1926 2674.26,1940.97 2751.03,1940.97 v2(2756,1936)
S\S\_\S\E\L\: IC7.42 U6.C16 | length 1701.2
  Top Layer LF-signals w6: v2(1953.67,1101) 1953.15,1101 U6.C16@1966.19,1114.05 ; v2(2937.4,490.28) IC7.42@2937.4,514.2
  Mid-1 w6: v2(1953.67,1101) 1944.65,1091.97 1944.65,508.35 1958.68,494.32 v2(1958.68,469)
  Mid-2 w6: v2(1958.68,469) 1984,469 1994.78,458.22 2906.04,458.22 2911.17,453.1 2926.83,453.1 2937.91,464.17 2937.91,489.77 v2(2937.4,490.28)
SCL: R001.1 U6.B8 U10.29 U12.6 U13.1 | length 1826.5
  Top Layer LF-signals w5: U6.B8@2218.16,1082.55 2233.91,1066.8 2233.91,1019.17
  Top Layer LF-signals w6: v2(930,974.11) 930,962.71 925.82,958.53 U10.29@1000.8,958.53 ; v2@2139.42,800 v2(2140.88,801.45) U12.6@2185.36,801.45 2253.62,801.45 U13.1@2259.53,807.36 2259.53,854.66 2233.91,880.28 2233.91,1019.17
  Mid-2 w6: v2(930,974.11) 1144.84,759.28 1879.77,759.28 1921.95,801.45 v2(2140.88,801.45)
  Signal Layer 1 w6: v2@929,975.11 v2(930,974.11)
SCLK: IC7.41 U6.J14 | length 1799.6
  Top Layer LF-signals w5: U6.J14@2029.19,1303.02 2030.18,1303.02 2040.16,1313 v2(2042,1313)
  Top Layer LF-signals w6: IC7.41@2917.72,514.2 2917.72,473.28 v2(2919,472)
  Mid-1 w6: v2@2029,472 v2(2029,475) 2028.91,475.1 2028.91,1169.59 2026.09,1172.4 2026.09,1297.1 v2(2042,1313)
  Mid-2 w6: v2@2029,474.82 2904.92,474.82 2907.74,472 v2(2919,472)
SDA: R002.1 U6.A10 U10.30 U12.5 U13.3 | length 1811.5
  Top Layer LF-signals w6: v2@925.35,919.65 R002.1@925.35,933 925.41,932.94 U10.30@1000.8,932.94 ; U6.A10@2155.17,1051.06 2155.17,942.17 2123.59,910.59 2123.59,769.41 v2(2141.55,751.45) U12.5@2185.36,751.45 ; U12.5@2190.09,756.18 U13.3@2259.53,756.18
  Top Layer LF-signals w7: v2@925.35,919.65 v2(928,917)
  Mid-2 w6: v2(928,917) 1097.63,747.37 2137.46,747.37 v2(2141.55,751.45)
SNS0V95-N: P-ADC.20 R79.1 | length 132.7
  Bottom Layer LF-signals w12: P-ADC.20@1431.41,386 1431.41,438.63 R79.1@1488,495.22
SNS0V95-P: P-ADC.19@1431.41,286 R78.1 | length 92.9
  Bottom Layer LF-signals w12: P-ADC.19@1431.41,286 1431.41,222.91 R78.1@1452.51,201.81
SNS5V0-N: P-ADC.16 R75.1 | length 234.7
  Bottom Layer LF-signals w6: R75.1@1513,200.34 1580,267.34 1580,334.59 P-ADC.16@1631.41,386
SNS5V0-P: P-ADC.15 R74.1 | length 110.5
  Bottom Layer LF-signals w12: R74.1@1556,202.79 1622,268.79 P-ADC.15@1622,286
T0: U6.M17 U10.23 | length 1381.5
  Top Layer LF-signals w5: 1871.31,1413.26 1918.95,1413.26 U6.M17@1934.7,1397.51
  Top Layer LF-signals w6: v2@959.07,1112.07 U10.23@1000.8,1112.07 ; v2@1764.91,1332 1789,1356.1 1789,1382.19 1811.16,1404.35 1811.16,1415.52 1811.09,1415.59 1811.09,1428.77 1820.41,1438.08 1833.59,1438.08 1842.91,1428.77 1842.91,1415.72 1845.37,1413.26 1871.31,1413.26
  Signal Layer 1 w6: v2(958,1111) 958,1208.49 1203.06,1453.55 1493.77,1453.55 1554.41,1392.91 1577.6,1392.91 1652.41,1318.1 1654.22,1318.1 1654.41,1317.91 1667.59,1317.91 1673.49,1312 1744,1312 v2(1764,1332)
TCK: DA.2 R147.1 U6.E10 U8.16 | length 1902.4
  Top Layer LF-signals w5: DA.2@1543.66,1924.08 R147.1@1543.66,1978
  Top Layer LF-signals w6: v2(1518,1945.94) DA.2@1541.76,1922.18 ; U6.E10@2155.17,1177.04 v2(2165.93,1187.8)
  Mid-1 w6: v2(1518,1945.94) 1576.91,1887.04 1576.91,1161.66 1547.24,1132 v2(1535,1132) v2@1535,1130.1
  Mid-2 w6: v2@2164.79,1188.95 v2(2165.93,1187.8)
  Signal Layer 1 w6: v2(1336,1178) 1352.66,1178 1398.66,1132 v2(1535,1132) 1592,1132 1658.53,1198.53 1785.59,1198.53 1815.12,1169 1852.49,1169 1862.4,1178.91 2015.18,1178.91 2024.07,1187.8 2051.69,1187.8 2059.94,1179.56 2157.69,1179.56 v2(2165.93,1187.8)
  Bottom Layer LF-signals w6: v2@1336.4,1178.4 U8.16@1336.4,1208.31
TDI: DC.2 R145.1 U6.E11 U8.14 | length 1944.7
  Top Layer LF-signals w6: v2(1284,1897) 1284,1911.81 1294,1921.81 1294,1958.78 R145.1@1313.22,1978 ; v2@2113,1162.86 v2(2111.27,1161.13) 2111.27,1164.64 U6.E11@2123.67,1177.04
  Mid-1 w6: v2(1284,1897) 1284,1874.99 1311.58,1847.41 1311.58,1743.75 1329.7,1725.63 1329.7,1445.47 1321.6,1437.36 1321.6,1407.1 1306,1391.51 1306,1111 v2(1314.91,1102.1)
  Mid-2 w6: v2(1314.91,1102.1) 1634.41,1102.1 1640.41,1096.1 1653.59,1096.1 1703.59,1146.1 1787.93,1146.1 1803.74,1161.91 1861.59,1161.91 1877.33,1146.16 2072.25,1146.16 2079.41,1139 2089.14,1139 v2(2111.27,1161.13)
  Bottom Layer LF-signals w6: v2(1314.91,1102.1) 1356.76,1102.1 1375.8,1121.14 U8.14@1375.8,1208.31
TDO: DB.2 R146.1 U6.E13 U8.25 | length 1735.2
  Top Layer LF-signals w5: DB.2@1418.07,1922.18 1418.07,1944.07 1428.44,1954.44 R146.1@1428.44,1969.38
  Top Layer LF-signals w6: v2(1393,1912) 1396,1915 1410.89,1915 DB.2@1418.07,1922.18 ; v2(2050,1167) 2050.64,1167 U6.E13@2060.68,1177.04
  Mid-1 w6: v2(1331,1132) 1318,1145 1318,1371 1337.5,1390.5 v2(1337.5,1430.77) 1341.61,1434.88 1341.61,1730.56 1323.48,1748.68 1323.48,1842.48 v2(1393,1912)
  Signal Layer 1 w6: v2(1331,1132) 1348.08,1149.08 1354.57,1149.08 1390.65,1113 1589.84,1113 1630.74,1153.91 1660.59,1153.91 1684.4,1130.1 1861.59,1130.1 1877.19,1145.7 1925.54,1145.7 1925.7,1145.54 2028.54,1145.54 v2(2050,1167)
  Bottom Layer LF-signals w6: U8.25@1336.4,1406.31 1336.4,1429.67 v2(1337.5,1430.77)
TDX0: U10.40
TMS: DD.2 R144.1 U6.E12 U8.15 | length 2076.6
  Top Layer LF-signals w5: DD.2@1170.67,1922.18 1170.67,1950.67 R144.1@1198,1978
  Top Layer LF-signals w6: v2(1148,1901) 1169.18,1922.18 DD.2@1170.67,1922.18 ; v2@2080.27,1161.13 v2(2079.77,1161.13) 2079.77,1164.64 U6.E12@2092.18,1177.04
  Mid-1 w6: v2(1148,1901) 1174.91,1927.91 1408.09,1927.91 1420.16,1915.84 1420.16,1886.66 1395.5,1862 1395.5,1803.5 1375.91,1783.91 1375.91,1754.78 1355.07,1733.94 v2(1355.07,1126.1)
  Signal Layer 1 w6: v2(1355.07,1126.1) 1353.56,1127.6 1353.56,1129 1386.47,1096.1 1666.09,1096.1 1683.89,1113.89 1933.89,1113.89 1953,1133 2051.64,1133 v2(2079.77,1161.13)
  Bottom Layer LF-signals w6: v2@1356.1,1127.13 U8.15@1356.1,1208.31
TXCLKA_N: IC7A.25 U6.M1 | length 1294.3
  Top Layer LF-signals w6.5: U6.M1@2438.63,1397.51 2451.41,1384.74 v2(2454.99,1384.74) 2456.74,1384.74 v2@2457,1385 ; v2(2736,2058) 2739.26,2054.74 IC7A.25@2809.43,2054.74
  Signal Layer 1 w5: v2(2454.99,1384.74) 2473.96,1384.74 2482,1376.7 2482,1351.33 2466.13,1335.47 2444.69,1335.47 2408.15,1372 2371.48,1372 2258.5,1484.98 2258.5,1496.99 2248.5,1506.99 2248.5,1676.73 2528.77,1957 2646.45,1957 2723,2033.55 2723,2045 v2(2736,2058)
TXCLKA_P: IC7A.26 U6.L1 | length 1196.5
  Top Layer LF-signals w6.5: U6.L1@2438.63,1366.02 2452.98,1366.02 v2(2454,1365) ; v2(2742.3,2038) 2745.24,2035.06 IC7A.26@2809.43,2035.06
  Signal Layer 1 w5: v2@2454.99,1364.02 v2(2454,1365) 2467.32,1365 2471,1361.32 2471,1355.18 2462.82,1347 2448,1347 2412.5,1382.5 2375.83,1382.5 2269,1489.33 2269,1501.34 2259,1511.34 2259,1672.38 2533.12,1946.5 2650.8,1946.5 v2(2742.3,2038)
TXCLKN: IC7.25 U6.V1 | length 1141.6
  Top Layer LF-signals w6.5: U6.V1@2438.63,1586.49 2441.88,1583.24 v2(2473,1583.24) ; v2(2740,759) 2746,759 2746.28,759.28 IC7.25@2810.43,759.28
  Signal Layer 1 w5: v2(2473,1583.24) 2490.26,1583.24 2503.5,1570 2651.85,1570 2730.6,1491.25 2730.6,762.4 2734,759 v2(2740,759)
TXCLKP: IC7.26 U6.U1 | length 1165.2
  Top Layer LF-signals w6.5: U6.U1@2438.63,1554.99 2448.77,1554.99 2452.02,1558.24 v2(2473,1558.24) ; v2(2720,739) 2720,735.1 2720.7,734.4 2725.89,739.59 IC7.26@2810.43,739.59
  Signal Layer 1 w5: v2(2473,1558.24) 2473.46,1558.24 2483.22,1568 2490.65,1568 2499.15,1559.5 2647.5,1559.5 2720.1,1486.9 2720,1486.8 v2(2720,739)
TXD0: U6.A9
TXDA_N: IC7A.27 U6.L3 | length 1393.5
  Top Layer LF-signals w6.5: U6.L3@2375.64,1366.02 2377.98,1366.02 v2(2387,1357) v2@2386,1357 ; v2(2763,2016) 2789.03,2016 2791.03,2014 2792.4,2015.37 IC7A.27@2809.43,2015.37
  Signal Layer 1 w5: v2(2387,1357) 2388.05,1357 2418.7,1326.35 2418.7,1313.35 2405.35,1300 2376,1300 2358,1318 2358,1356.49 2238,1476.49 2238,1488.5 2228,1498.5 2228,1685.23 2521.28,1978.5 2612.64,1978.5 2613.14,1979 ; 2613.15,1979 2722.65,2088.5 2745.35,2088.5 2779,2054.85 2779,2032 v2(2763,2016)
TXDA_P: IC7A.28 U6.K3 | length 1335.5
  Top Layer LF-signals w6.5: U6.K3@2375.64,1334.52 v2(2386.16,1324) ; v2(2755,1996.03) 2788.01,1996.03 2790.03,1994 2792.06,1996.03 2792.4,1995.69 IC7A.28@2809.43,1995.69
  Signal Layer 1 w5: v2(2386.16,1324) 2394.16,1332 2398.2,1332 2408.2,1322 2408.2,1317.7 2401,1310.5 2380.35,1310.5 2368.5,1322.35 2368.5,1360.84 2248.5,1480.84 2248.5,1492.85 2238.5,1502.85 2238.5,1680.88 2525.63,1968 2616.99,1968 2617.49,1968.5 ; 2617.5,1968.5 2727,2078 2741,2078 2766.94,2052.06 2766.94,2042.14 2755.98,2031.17 2748.31,2023.5 2748,2023.5 2748,2003.03 v2(2755,1996.03)
TXDN: IC7.27 U6.U3 | length 1257.1
  Top Layer LF-signals w6.5: U6.U3@2375.64,1554.99 v2(2389,1568.35) ; v2(2738,719) 2738.91,719.91 IC7.27@2810.43,719.91
  Signal Layer 1 w5: v2(2389,1568.35) 2388,1567.35 2388,1544 2391.5,1540.5 2639.35,1540.5 2699.5,1480.35 2699.5,728.87 2719.87,708.5 2724.29,708.5 2728.79,713 2730.52,713 2736.52,719 v2(2738,719)
TXDP: IC7.28 U6.U4 | length 1285.9
  Top Layer LF-signals w6.5: U6.U4@2344.15,1554.99 2344.15,1555.15 v2(2358,1569) ; v2(2735,698) 2735,695 2740.22,700.22 IC7.28@2810.43,700.22
  Signal Layer 1 w5: v2(2358,1569) 2361,1569 2375.15,1554.85 2375.15,1542 2387.15,1530 2635,1530 2689,1476 2689,724.52 2715.52,698 v2(2735,698)
VCC: C001.1 C26.1 C31.1 C41.1 D001.2 JP1.1 U1.2 U1.6 U3.2 U3.6 U5.1
  other v3: 301.1,191.98 232,736 687,848 235.01,1933.55 636,1983
VCC0-AB: C49.1 C50.1 C77.1 C78.1 R26.2
VCC0-CD: C51.1 C52.1 C63.1 C64.1 R27.2
VCC_3V3: C13.1 C13A.1 C14.1 C14A.1 C15.1 C15A.1 C16.1 C16A.1 C17.1 C17A.1 C23.1 C230.1 IC7.15 IC7.21 IC7.29 IC7.39 IC7.46 IC7A.15 IC7A.21 IC7A.29 IC7A.39 IC7A.46 J1.1 J10.1 JP.2 W1.2 | length 8568.8
  Top Layer LF-signals w5: IC7.39@2878.35,514.2 C17.1@2878.35,425.08 ; C17.1@2883.27,430 C17.1@2878.35,425.08 ; C17A.1@3076,2144.66 3086.49,2144.66 ; C17.1@2878.35,425.08 2878,424.73 v1(2878,410) 2878.35,410.35 C17.1@2878.35,425.08
  Top Layer LF-signals w7: C230.1@2717.46,1976 IC7A.29@2809.43,1976 ; v1(2721,654) 2719,656 2719,656.1 C15.1@2738.91,676 ; C15.1@2743.44,680.54 IC7.29@2810.43,680.54 ; C13A.1@2867,1756 2877.35,1766.35 IC7A.39@2877.35,1809.66 ; v1(2886,909) 2886,863.25 C13.1@2905.9,843.34 2898.03,835.47 IC7.21@2898.03,787.82 ; v1(2889,2217) 2889.75,2216.25 2889.75,2154.25 2907,2137 2907,2123 2897.03,2113.03 IC7A.21@2897.03,2083.28 ; C16A.1@2992,1754 3015.14,1777.14 IC7A.46@3015.14,1809.66 ; IC7A.15@3015.14,2083.28 3015.14,2101.09 3026,2111.95 3026,2120 3050.64,2144.64 3068.35,2144.64 C17A.1@3076,2136.99 ; IC7.46@3016.14,514.2 3016.14,471.65 C16.1@3004.49,460 v1(3022,460) v1@3021.42,459.42 ; IC7.15@3016.14,787.82 v1(3016.14,812) ; v1@3095.06,2154.59 v1(3096.41,2154.59)
  Top Layer LF-signals w12: v1@2878.35,410.35 2883.27,415.27 C17.1@2883.27,430 ; 3086.49,2144.66 v1(3096.41,2154.59)
  Top Layer LF-signals w20: v1@2690,2462.41 v1(2690.71,2461.7) C14A.1@2690.71,2434.37 ; C230.1@2716.46,1977 v1(2716.46,1912.54) v1@2717,1912 ; C13A.1@2867,1756 2881.92,1756 2912,1725.92 v1(2912,1722) v1@2911.57,1722.43 ; v1(2960,1702) 2960,1724.81 2989.19,1754 C16A.1@2992,1754
  Top Layer LF-signals w40: J1.1@3239.83,152.47 C23.1@3319,152.47
  Bottom Layer LF-signals w12: JP.2@2593,272 2516,349 2516,484 2686,654 v1(2721,654) ; v1(2886,909) 2983,812 v1(3016.14,812) ; v1(3096.41,2154.59) 3096.41,2115.12 3239.85,1971.68 3239.85,1968.5
  Bottom Layer LF-signals w40: v1(2690.71,2461.7) 2735.01,2506 3156.5,2506 J10.1@3238,2424.5 ; v1(2878,410) 2838.3,449.7 2770.7,449.7 JP.2@2593,272 2644.23,220.78 2902.23,220.78 2963.7,159.3 J1.1@3233,159.3 ; 2947.55,1707.47 2864.53,1707.47 2704,1868 2704,2114 2813.39,2223.39 2882.61,2223.39 2971.27,2312.05 3060.61,2312.05 3173.07,2424.5 J10.1@3238,2424.5 ; v1(3016.14,812) 3016.14,796.23 3195.03,617.35 3349.8,617.35 ; v1(3022,460) 3022,383 3233,172 J1.1@3233,159.3 ; 3149.61,1227 3149.61,1878.26 3239.85,1968.5 3314.16,2042.82 3314.16,2348.34 J10.1@3238,2424.5 ; 3168,1239 3314.16,1239 3425,1128.17 3425,992.49 3349.8,917.29 3349.8,617.35 ; J1.1@3233,159.3 3268.3,159.3 3349.8,240.8 3349.8,617.35
  other v1: 3158,1218.6 3179,1230
VCC_B_3.3V: C9.1 J1.2 J10.2 L2.1 L20.1 W2.2 | length 4484
  Top Layer LF-signals w11.81: C9.1@2810.43,1345.34 2843.61,1345.34 W2.2@2881.44,1383.17
  Top Layer LF-signals w12: v1(2687,2189) 2687,2191 2673,2205 2586,2205 2521.28,2269.72 2521.28,2436.28 2661,2576 2943.97,2576 L20.1@2978.67,2541.3 J10.2@3221.2,2541.3 ; C9.1@2810.43,1345.34 2810.43,1372.34 v1(2831,1392.91) ; v1(3084,86) 3097.98,86 L2.1@3120.29,108.32 3120.29,120.29 3144,144 3175.25,144 3188.34,130.91 3188.34,103.96 J1.2@3233,59.3
  Bottom Layer LF-signals w12: v1(2687,2189) 2687,2164 2588.91,2065.91 2588.91,1689.07 2831,1446.98 v1@2831,1401 ; 2831,1423 v1@2831,1401 ; v1(3084,86) 3081.37,88.63 2661.35,88.63 2494.55,255.43 2494.55,638.55 2814.91,958.91 2814.91,1162.07 2754,1222.98 2754,1359.1 2787.8,1392.91 v1(2831,1392.91) v1@2831,1401
VCC_TARGET: C1.2 C1A.2 C11.2 C110.2 D1A.2 D2.2 D2A.2 IC2.4 IC2A.4 L2.2 L20.2 R1A.2 R101.2 R101A.2 R102.2 R102A.2 | length 4101.8
  Top Layer LF-signals w20: v1(2577,2300.02) IC2A.4@2607.86,2269.16 ; R102.2@2722,88.63 D2.2@2923.62,88.63 ; IC2.4@2783.34,274.65 C1.2@2783.34,330 ; IC2.4@2787.54,270.46 2884,173.99 2884,128.25 D2.2@2923.62,88.63 ; L2.2@3161.63,108.32 3161.63,53.63 3137,29 2983.25,29 D2.2@2923.62,88.63
  Bottom Layer LF-signals w12: v1(2577,2300.02) 2648.5,2371.52 2700.94,2371.52 v1(2732.71,2403.29)
  Bottom Layer LF-signals w20: v1(2732.71,2403.29) 2752.71,2423.29 ; 2769,64 2655,64 2472.64,246.36 2472.64,677.64 2793,998 2793,1153 2711,1235 2711,1536 2556,1691 2556,2176.78 2752.71,2373.49 2752.71,2423.29 ; v1(2897.71,2429.29) 2758.71,2429.29 2752.71,2423.29
  other v1: 2724,64 2751,64 2731.71,2433.29 2896.71,2460.29
VIN: JP1.3
VSNS5V0-N: P-ADC.14 R73.1 | length 126
  Bottom Layer LF-signals w12: P-ADC.14@1731.41,386 1731.41,437.7 1757.44,463.72 R73.1@1757.44,501.27
VSNS5V0-P: P-ADC.13 R72.1 | length 110.8
  Bottom Layer LF-signals w12: R72.1@1667.16,201.81 1731.41,266.06 P-ADC.13@1731.41,286
VSNSVU-N: P-ADC.18 R77.1 | length 155.1
  Bottom Layer LF-signals w12: P-ADC.18@1531.41,386 1629,483.59 R77.1@1629,500.66
VSNSVU-P: P-ADC.17 R76.1 | length 259.5
  Bottom Layer LF-signals w6: P-ADC.17@1531.41,286 1485,332.41 1485,457 R76.1@1534,506
VUSB: CON2.1 JP1.2
pads on no net: B1.6 B1A.6 CON2. CON2.4 CON2.6 CON2.7 CON2.8 CON2.9 IC7.4.8 IC7.10@2986.61,611.64 IC7.11@2986.61,690.38 IC7.12@2906.89,689.39 IC7.13@2907.87,611.64 IC7.14@2947.24,611.64 IC7.16@2986.61,651.01 IC7.17@2907.87,651.01 IC7A.4.8 IC7A.10@2985.61,1907.1 IC7A.11@2985.61,1985.84 IC7A.12@2905.89,1984.86 IC7A.13@2906.87,1907.1 IC7A.14@2946.24,1907.1 IC7A.16@2985.61,1946.47 IC7A.17@2906.87,1946.47 IC8.0 IC8.6 P-ADC.19@1431.41,286 P-ADC.19@1431.41,386 P-ADC.19@1531.41,286 P-ADC.19@1531.41,386 P-ADC.19@1631.41,286 P-ADC.19@1631.41,386 P-ADC.19@1731.41,286 P-ADC.19@1731.41,386 P-ADC.19@1831.41,286 P-ADC.19@1831.41,386 P-ADC.19@1931.41,286 P-ADC.19@1931.41,386 P-ADC.19@2031.41,286 P-ADC.19@2031.41,386 P-ADC.19@2131.41,286 P-ADC.19@2131.41,386 P-ADC.19@2231.41,286 P-ADC.19@2231.41,386 P-ADC.19@2331.41,286 P-ADC.19@2331.41,386 Pio.19@1458.95,2289.4 Pio.19@1458.95,2389.4 Pio.19@1558.95,2289.4 Pio.19@1558.95,2389.4 Pio.19@1658.95,2289.4 Pio.19@1658.95,2389.4 Pio.19@1758.95,2289.4 Pio.19@1758.95,2389.4 Pio.19@1858.95,2289.4 Pio.19@1858.95,2389.4 Pio.19@1958.95,2289.4 Pio.19@1958.95,2389.4 Pio.19@2058.95,2289.4 Pio.19@2058.95,2389.4 Pio.19@2158.95,2289.4 Pio.19@2158.95,2389.4 Pio.19@2258.95,2289.4 Pio.19@2258.95,2389.4 Pio.19@2358.95,2289.4 Pio.19@2358.95,2389.4 U1.8 U3.8 U6.A11 U6.A13 U6.A14 U6.A18 U6.B9 U6.B11 U6.B13 U6.B14 U6.B18 U6.C9 U6.C10 U6.C11 U6.D2 U6.D3 U6.D5 U6.D9 U6.D12 U6.D13 U6.D15 U6.E7 U6.E8 U6.E15 U6.E16 U6.F5 U6.G3 U6.G13 U6.H4 U6.H5 U6.H6 U6.H9 U6.H10 U6.H15 U6.J4 U6.J5 U6.J10 U6.J13 U6.J15 U6.J18 U6.K1 U6.K2 U6.K6 U6.K9 U6.K15 U6.K16 U6.L5 U6.L6 U6.L9 U6.L10 U6.M4 U6.M6 U6.N4 U6.N5 U6.N6 U6.P2 U6.P4 U6.R1 U6.R2 U6.R5 U6.R6 U6.R7 U6.R8 U6.T1 U6.T4 U6.T5 U6.T6 U6.T8 U6.U6 U6.U7 U6.U8 U6.U9 U6.V6 U6.V7 U6.V9 U8.3 U8.22 U8.28 U8.30 U8.33 U10.13 U10.14 U10.15 U10.24 U10.25 U10.27 U10.28 U10.31 U10.32 U10.42 U10.43 U10.79 XC1.1 XC2.1 XL1.4
copper on no net:
  other v1: 112.19,557

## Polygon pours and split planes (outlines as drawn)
GND on Top Layer LF-signals "TOP" (solid, pour order 7): 39.37,39.39 39.37,2561.97 4022,2561.97 4022,39.39
GND on Bottom Layer LF-signals "BOTTOM" (solid, pour order 7): 36.37,49.48 36.37,2572.06 4023,2572.06 4023,49.48
GND on Signal Layer 1 "S1" (solid, pour order 7): 39.37,39.39 39.37,2561.97 4022,2561.97 4022,39.39
GND on Mid-1 "M1" (solid, pour order 7): 39.37,39.39 39.37,2561.97 4024,2561.97 4024,39.39
GND on Mid-2 "M2" (solid, pour order 7): 39.37,39.39 39.37,2561.97 4024,2561.97 4024,39.39
GND on Internal Plane 1 (split plane): 4035.64,20.1 20.1,20.1 20.1,2585.9 4035.64,2585.9

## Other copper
Top Layer LF-signals:
  region net VCC: 228.81,191.81 187.8,232.81 160,205 201,164
  rectangle net VCC: 159,204 229,826.47
  rectangle net VCC: 201,164 330,221
  rectangle net VCC: 563,793 584,873.8
  rectangle net VCC: 331,1554.85 459,1663.89
  rectangle net VCC: 397,807.36 459,1605
  rectangle net VCC: 196,695 270,827
  rectangle net VCC: 196,778 715.76,827
  rectangle net VCC: 584,827 714,873.8
  rectangle net VCC: 199,1554 334,1962
  rectangle net VCC: 199,1891 269,2015.37
  rectangle net VCC: 199,1952.88 685,2018
  rectangle net NetD2A_1: 2877,2286.95 2957,2320
  rectangle net GND: 512,275 571.6,343
  rectangle net GND: 567,181 592.83,343
  rectangle net VCC0-CD: 610,195 636,382
  rectangle net VCC0-AB: 414.3,285 491,312
  rectangle net VCC0-AB: 472.12,271 495,388
  rectangle net VCC0-AB: 257,263.1 425,312
  rectangle net VUSB: 137,1345.99 253,1362
  rectangle net VUSB: 230.25,1347 253,1505.84
  rectangle net VUSB: 230.25,1458 326,1523.5
  region net 1V8: 2114.3,1377.89 2110.64,1379.22 2106.06,1366.64 2109.72,1365.31
  rectangle net VCC_3V3: 3131,1206 3218,1240
  rectangle net 2V5: 2617,1674 2644.19,1696
  rectangle net 3V3: 2315,626 2369,830
  rectangle net VCC_TARGET: 2923.62,2486 3053,2513
  rectangle net VCC_TARGET: 2999,2432 3053,2512
  rectangle net VCC_TARGET: 2870,2343 2955,2358
  rectangle net VCC_TARGET: 2872,2341 2923.62,2513
  rectangle net VCC_TARGET: 2722.65,2372.17 2757,2459
  rectangle net 3V3: 768,554 893,667
  rectangle net 3V3: 2063,632 2110.26,924
  rectangle net 3V3: 1723,825 1844.91,866
  rectangle net 3V3: 1706,642.91 1763.43,864
  rectangle net 3V3: 2315,624 2581,753
  rectangle net GND: 137,1243.53 333,1260
  rectangle net GND: 287,1205 339,1260
  rectangle net GND: 1699,967.89 1727.92,990
  rectangle net NetR45_2: 1367,94 1412,116
  rectangle net GND: 3677,1671.2 3858.27,1819.98
  rectangle net VCC_TARGET: 2709.84,51 2776,98
  rectangle net GND: 2324,895 2331.41,903
  pour cut-out: 1875,1613.6 1875.45,1614.05 2466.19,1614.05 2466.19,1023.5 1875.64,1023.5 1875.64,1614.05
  pour cut-out: 2538.72,1233.43 2629.28,1233.43 2629.28,1162.57 2538.72,1162.57
  pour cut-out: 1692.3,1568.05 1692.3,1658.61 1763.17,1658.61 1763.17,1568.05
  pour cut-out: 836.01,1489.99 838.47,1487.53 909.34,1487.53 909.34,1387 907.79,1385.46 829.33,1385.46 829.33,1483.31
Mid-1:
  pour cut-out: 1875,1613.6 1875.45,1614.05 2466.19,1614.05 2466.19,1023.5 1875.64,1023.5 1875.64,1614.05
  pour cut-out: 2538.72,1233.43 2629.28,1233.43 2629.28,1162.57 2538.72,1162.57
  pour cut-out: 1692.3,1568.05 1692.3,1658.61 1763.17,1658.61 1763.17,1568.05
  pour cut-out: 836.01,1489.99 838.47,1487.53 909.34,1487.53 909.34,1387 907.79,1385.46 829.33,1385.46 829.33,1483.31
Mid-2:
  rectangle net 2V5: 793,1752 922,1815
  pour cut-out: 1875,1613.6 1875.45,1614.05 2466.19,1614.05 2466.19,1023.5 1875.64,1023.5 1875.64,1614.05
  pour cut-out: 2538.72,1233.43 2629.28,1233.43 2629.28,1162.57 2538.72,1162.57
  pour cut-out: 1692.3,1568.05 1692.3,1658.61 1763.17,1658.61 1763.17,1568.05
  pour cut-out: 836.01,1489.99 838.47,1487.53 909.34,1487.53 909.34,1387 907.79,1385.46 829.33,1385.46 829.33,1483.31
Signal Layer 1:
  rectangle net 3V3: 2092,859 2155,929.17
  pour cut-out: 1875,1613.6 1875.45,1614.05 2466.19,1614.05 2466.19,1023.5 1875.64,1023.5 1875.64,1614.05
  pour cut-out: 2538.72,1233.43 2629.28,1233.43 2629.28,1162.57 2538.72,1162.57
  pour cut-out: 1692.3,1568.05 1692.3,1658.61 1763.17,1658.61 1763.17,1568.05
  pour cut-out: 836.01,1489.99 838.47,1487.53 909.34,1487.53 909.34,1387 907.79,1385.46 829.33,1385.46 829.33,1483.31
